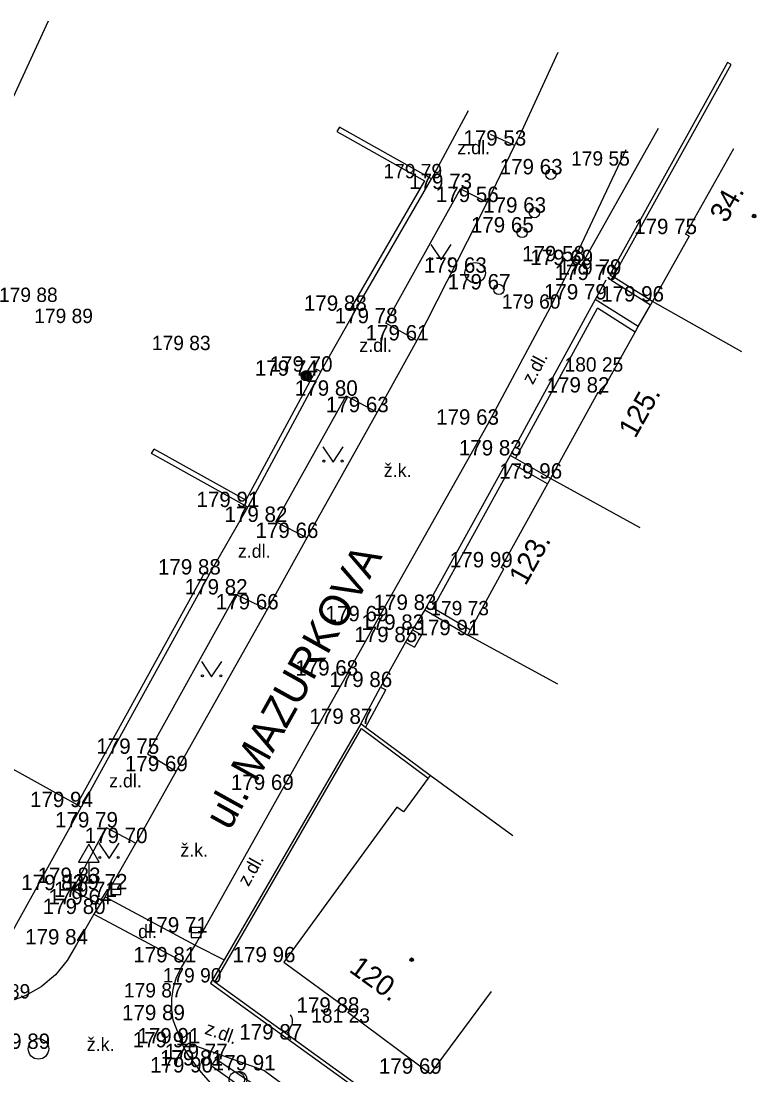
# Model space of a CAD drawing. Extents: x -537755 to -537431, y -1180722 to -1180510.
# Drawn here: x -537645.9 to -537610, y -1180566.9 to -1180515.4 of the extents above; entities that cross this region are included whole.
import ezdxf

# ---------------------------------------------------------------- set-up
doc = ezdxf.new("R2010")
doc.units = 0
for name, color, linetype in [('Vrstva 1', 7, 'Continuous'), ('Vrstva 10', 7, 'Continuous'), ('Vrstva 11', 7, 'Continuous'), ('Vrstva 21', 7, 'Continuous'), ('Vrstva 24', 7, 'Continuous'), ('Vrstva 25', 7, 'Continuous'), ('Vrstva 27', 7, 'Continuous'), ('Vrstva 28', 7, 'Continuous'), ('Vrstva 3', 7, 'Continuous'), ('Vrstva 34', 7, 'Continuous'), ('Vrstva 36', 7, 'Continuous'), ('Vrstva 39', 7, 'Continuous'), ('Vrstva 40', 7, 'Continuous'), ('Vrstva 47', 7, 'Continuous'), ('Vrstva 49', 7, 'Continuous'), ('Vrstva 5', 7, 'Continuous'), ('Vrstva 7', 7, 'Continuous'), ('Vrstva 8', 7, 'Continuous')]:
    doc.layers.add(name, color=color, linetype=linetype)

msp = doc.modelspace()

# ---------------------------------------------------------------- linework, layer by layer
at = {"layer": 'Vrstva 1'}
for p, q in [((-537621.821, -1180521.513), (-537621.821, -1180521.513)), ((-537616.732, -1180522.488), (-537616.732, -1180522.488)), ((-537625.887, -1180523.104), (-537625.887, -1180523.104)), ((-537625.88, -1180523.14), (-537625.88, -1180523.14)), ((-537620.049, -1180522.914), (-537620.049, -1180522.914)), ((-537624.465, -1180523.627), (-537624.465, -1180523.627)), ((-537623.163, -1180524.264), (-537623.163, -1180524.264)), ((-537620.853, -1180524.784), (-537620.853, -1180524.784)), ((-537621.51, -1180525.74), (-537621.51, -1180525.74)), ((-537621.455, -1180525.751), (-537621.455, -1180525.751)), ((-537613.49, -1180525.83), (-537613.49, -1180525.83)), ((-537618.955, -1180527.156), (-537618.955, -1180527.156)), ((-537623.746, -1180527.714), (-537623.746, -1180527.714)), ((-537618.559, -1180527.34), (-537618.559, -1180527.34)), ((-537617.18, -1180527.81), (-537617.18, -1180527.81)), ((-537617.37, -1180528.07), (-537617.37, -1180528.07)), ((-537622.587, -1180528.528), (-537622.587, -1180528.528)), ((-537644.64, -1180529.14), (-537644.64, -1180529.14)), ((-537617.89, -1180529.02), (-537617.89, -1180529.02)), ((-537615.1, -1180529.12), (-537615.1, -1180529.12)), ((-537629.6, -1180529.57), (-537629.6, -1180529.57)), ((-537620.113, -1180529.467), (-537620.113, -1180529.467)), ((-537642.92, -1180530.17), (-537642.92, -1180530.17)), ((-537628.097, -1180530.179), (-537628.097, -1180530.179)), ((-537626.588, -1180531.018), (-537626.588, -1180531.018)), ((-537637.18, -1180531.49), (-537637.18, -1180531.49)), ((-537632.19, -1180532.84), (-537632.19, -1180532.84)), ((-537631.99, -1180532.74), (-537631.99, -1180532.74)), ((-537631.27, -1180532.54), (-537631.27, -1180532.54)), ((-537617.05, -1180532.54), (-537617.05, -1180532.54)), ((-537630.041, -1180533.715), (-537630.041, -1180533.715)), ((-537617.76, -1180533.56), (-537617.76, -1180533.56)), ((-537628.528, -1180534.519), (-537628.528, -1180534.519)), ((-537623.36, -1180535.47), (-537623.36, -1180535.47)), ((-537623.15, -1180535.129), (-537623.15, -1180535.129)), ((-537629.16, -1180535.58), (-537629.16, -1180535.58)), ((-537622.04, -1180536.63), (-537622.04, -1180536.63)), ((-537620.07, -1180537.76), (-537620.07, -1180537.76)), ((-537634.84, -1180539.15), (-537634.84, -1180539.15)), ((-537633.472, -1180539.873), (-537633.472, -1180539.873)), ((-537631.96, -1180540.657), (-537631.96, -1180540.657)), ((-537622.48, -1180542.09), (-537622.48, -1180542.09)), ((-537636.72, -1180542.44), (-537636.72, -1180542.44)), ((-537635.415, -1180543.413), (-537635.415, -1180543.413)), ((-537633.898, -1180544.141), (-537633.898, -1180544.141)), ((-537626.2, -1180544.17), (-537626.2, -1180544.17)), ((-537628.546, -1180544.722), (-537628.546, -1180544.722)), ((-537623.6, -1180544.43), (-537623.6, -1180544.43)), ((-537626.8, -1180545.14), (-537626.8, -1180545.14)), ((-537627.14, -1180545.74), (-537627.14, -1180545.74)), ((-537624.11, -1180545.4), (-537624.11, -1180545.4)), ((-537630.02, -1180547.37), (-537630.02, -1180547.37)), ((-537628.36, -1180547.93), (-537628.36, -1180547.93)), ((-537630.78, -1180548.65), (-537630.78, -1180548.65)), ((-537630.95, -1180549), (-537630.95, -1180549)), ((-537629.33, -1180549.73), (-537629.33, -1180549.73)), ((-537639.725, -1180551.19), (-537639.725, -1180551.19)), ((-537638.33, -1180552.039), (-537638.33, -1180552.039)), ((-537633.161, -1180552.953), (-537633.161, -1180552.953)), ((-537642.96, -1180553.79), (-537642.96, -1180553.79)), ((-537641.739, -1180554.78), (-537641.739, -1180554.78)), ((-537640.294, -1180555.547), (-537640.294, -1180555.547)), ((-537642.59, -1180557.49), (-537642.59, -1180557.49)), ((-537643.39, -1180557.84), (-537643.39, -1180557.84)), ((-537641.275, -1180557.801), (-537641.275, -1180557.801)), ((-537642.06, -1180558.54), (-537642.06, -1180558.54)), ((-537641.788, -1180558.176), (-537641.788, -1180558.176)), ((-537641.754, -1180558.18), (-537641.754, -1180558.18)), ((-537642.342, -1180559.006), (-537642.342, -1180559.006)), ((-537637.355, -1180559.909), (-537637.355, -1180559.909)), ((-537643.199, -1180560.493), (-537643.199, -1180560.493)), ((-537637.372, -1180560.473), (-537637.372, -1180560.473)), ((-537637.75, -1180561.22), (-537637.75, -1180561.22)), ((-537637.921, -1180561.366), (-537637.921, -1180561.366)), ((-537633.08, -1180561.36), (-537633.08, -1180561.36)), ((-537636.652, -1180562.347), (-537636.652, -1180562.347)), ((-537636.65, -1180562.38), (-537636.65, -1180562.38)), ((-537636.55, -1180562.35), (-537636.55, -1180562.35)), ((-537638.545, -1180563.077), (-537638.545, -1180563.077)), ((-537629.96, -1180563.82), (-537629.96, -1180563.82)), ((-537638.472, -1180564.188), (-537638.472, -1180564.188)), ((-537629.41, -1180564.31), (-537629.41, -1180564.31)), ((-537637.724, -1180565.319), (-537637.724, -1180565.319)), ((-537632.75, -1180565.13), (-537632.75, -1180565.13)), ((-537645.047, -1180565.588), (-537645.047, -1180565.588)), ((-537637.951, -1180565.512), (-537637.951, -1180565.512)), ((-537636.39, -1180566.09), (-537636.39, -1180566.09)), ((-537637.103, -1180566.74), (-537637.103, -1180566.74)), ((-537636.62, -1180566.4), (-537636.62, -1180566.4)), ((-537634.047, -1180566.636), (-537634.047, -1180566.636)), ((-537625.94, -1180566.8), (-537625.94, -1180566.8))]:
    msp.add_line(p, q, dxfattribs=at)
at = {"layer": 'Vrstva 10'}
for p, q in [((-537621.821, -1180521.513), (-537623.163, -1180524.264)), ((-537618.955, -1180527.156), (-537616.376, -1180521.7)), ((-537623.163, -1180524.264), (-537626.588, -1180531.018)), ((-537620.2, -1180529.637), (-537618.955, -1180527.156)), ((-537623.15, -1180535.129), (-537620.2, -1180529.637)), ((-537626.588, -1180531.018), (-537628.528, -1180534.519)), ((-537628.528, -1180534.519), (-537631.96, -1180540.657)), ((-537628.546, -1180544.722), (-537623.15, -1180535.129)), ((-537631.96, -1180540.657), (-537633.898, -1180544.141)), ((-537633.898, -1180544.141), (-537638.33, -1180552.039)), ((-537630.02, -1180547.37), (-537628.546, -1180544.722)), ((-537633.161, -1180552.953), (-537630.02, -1180547.37)), ((-537638.33, -1180552.039), (-537640.294, -1180555.547)), ((-537637.396, -1180560.52), (-537633.161, -1180552.953)), ((-537641.788, -1180558.176), (-537640.294, -1180555.547)), ((-537641.788, -1180558.176), (-537637.396, -1180560.52)), ((-537642.342, -1180559.006), (-537643.199, -1180560.493)), ((-537642.342, -1180559.006), (-537637.921, -1180561.366)), ((-537637.921, -1180561.366), (-537637.396, -1180560.52))]:
    msp.add_line(p, q, dxfattribs=at)
for points in [[(-537619.715, -1180516.973), (-537621.478, -1180520.825), (-537621.821, -1180521.513)], [(-537642.06, -1180558.54), (-537642.342, -1180559.006)], [(-537641.788, -1180558.176), (-537642.06, -1180558.54)], [(-537643.199, -1180560.493), (-537643.645, -1180561.278), (-537644.223, -1180561.973), (-537644.914, -1180562.555), (-537645.697, -1180563.006), (-537646.547, -1180563.313), (-537647.438, -1180563.465), (-537648.341, -1180563.458), (-537648.663, -1180563.416)], [(-537638.472, -1180564.188), (-537638.55, -1180563.66), (-537638.549, -1180563.127), (-537638.468, -1180562.599), (-537638.31, -1180562.09), (-537638.077, -1180561.61), (-537637.921, -1180561.366)], [(-537637.103, -1180566.74), (-537637.707, -1180565.933), (-537637.951, -1180565.512), (-537638.472, -1180564.188)], [(-537634.903, -1180568.594), (-537635.829, -1180567.981), (-537636.657, -1180567.242), (-537637.103, -1180566.74)]]:
    msp.add_lwpolyline(points, dxfattribs=at)
at = {"layer": 'Vrstva 11'}
for p, q in [((-537624.089, -1180519.81), (-537625.88, -1180523.14)), ((-537621.821, -1180521.513), (-537623.003, -1180520.976)), ((-537618.559, -1180527.34), (-537614.807, -1180520.662)), ((-537628.097, -1180530.179), (-537624.465, -1180523.627)), ((-537624.465, -1180523.627), (-537623.163, -1180524.264)), ((-537618.955, -1180527.156), (-537618.559, -1180527.34)), ((-537626.588, -1180531.018), (-537628.097, -1180530.179)), ((-537633.472, -1180539.873), (-537630.041, -1180533.715)), ((-537630.041, -1180533.715), (-537628.528, -1180534.519)), ((-537631.96, -1180540.657), (-537633.472, -1180539.873)), ((-537635.415, -1180543.413), (-537639.725, -1180551.19)), ((-537633.898, -1180544.141), (-537635.415, -1180543.413)), ((-537639.725, -1180551.19), (-537638.33, -1180552.039)), ((-537643.39, -1180557.84), (-537641.739, -1180554.78)), ((-537641.739, -1180554.78), (-537640.294, -1180555.547)), ((-537643.39, -1180557.84), (-537642.06, -1180558.54)), ((-537637.396, -1180560.52), (-537635.993, -1180561.245)), ((-537623.722, -1180574.291), (-537634.047, -1180566.636))]:
    msp.add_line(p, q, dxfattribs=at)
msp.add_lwpolyline([(-537634.047, -1180566.636), (-537637.724, -1180565.319), (-537637.951, -1180565.512)], dxfattribs=at)
at = {"layer": 'Vrstva 21'}
msp.add_lwpolyline([(-537636.62, -1180566.4), (-537634.122, -1180568.192), (-537633.84, -1180567.8), (-537636.39, -1180566.09), (-537636.62, -1180566.4)], dxfattribs=at)
at = {"layer": 'Vrstva 24'}
for centre, start, end in [((-537633.15, -1180564.231), 323.1301, 36.8699), ((-537632.35, -1180564.831), 143.1301, 216.8699)]:
    msp.add_arc(centre, 0.5, start, end, dxfattribs=at)
at = {"layer": 'Vrstva 25'}
for radius in [0.25, 0.2, 0.15, 0.1, 0.05]:
    msp.add_circle((-537631.99, -1180532.74), radius, dxfattribs=at)
at = {"layer": 'Vrstva 27'}
for p, q in [((-537641.525, -1180557.801), (-537641.025, -1180557.801)), ((-537637.605, -1180559.909), (-537637.105, -1180559.909))]:
    msp.add_line(p, q, dxfattribs=at)
for points in [[(-537641.525, -1180558.051), (-537641.025, -1180558.051), (-537641.025, -1180557.551), (-537641.525, -1180557.551)], [(-537637.605, -1180560.159), (-537637.105, -1180560.159), (-537637.105, -1180559.659), (-537637.605, -1180559.659)]]:
    msp.add_lwpolyline(points, close=True, dxfattribs=at)
for centre in [(-537623.746, -1180527.714), (-537645.047, -1180565.588)]:
    msp.add_circle(centre, 0.5, dxfattribs=at)
at = {"layer": 'Vrstva 28'}
for centre in [(-537620.049, -1180522.914), (-537620.853, -1180524.784), (-537621.455, -1180525.751), (-537622.587, -1180528.528)]:
    msp.add_circle(centre, 0.25, dxfattribs=at)
at = {"layer": 'Vrstva 34'}
for p, q in [((-537642.59, -1180556.474), (-537642.59, -1180557.49)), ((-537642.84, -1180557.49), (-537642.34, -1180557.49))]:
    msp.add_line(p, q, dxfattribs=at)
msp.add_lwpolyline([(-537643.09, -1180556.474), (-537642.09, -1180556.474), (-537642.59, -1180555.606)], close=True, dxfattribs=at)
at = {"layer": 'Vrstva 36'}
for points in [[(-537625.911, -1180526.333), (-537625.411, -1180527.083), (-537624.911, -1180526.333)], [(-537631.178, -1180536.202), (-537630.678, -1180536.952), (-537630.178, -1180536.202)], [(-537637.103, -1180546.685), (-537636.603, -1180547.435), (-537636.103, -1180546.685)], [(-537642.107, -1180555.55), (-537641.607, -1180556.3), (-537641.107, -1180555.55)]]:
    msp.add_lwpolyline(points, dxfattribs=at)
for centre, radius in [((-537625.861, -1180527.033), 0.05), ((-537624.962, -1180527.033), 0.05), ((-537631.128, -1180536.902), 0.05), ((-537630.229, -1180536.902), 0.05), ((-537637.053, -1180547.385), 0.05), ((-537636.154, -1180547.385), 0.05), ((-537642.057, -1180556.25), 0.05), ((-537641.158, -1180556.25), 0.05), ((-537635.371, -1180567.076), 0.375)]:
    msp.add_circle(centre, radius, dxfattribs=at)
msp.add_arc((-537635.246, -1180567.076), 0.375, 260.4059, 99.5941, dxfattribs=at)
at = {"layer": 'Vrstva 39'}
for centre, radius in [((-537610.139, -1180524.95), 0.09), ((-537610.139, -1180524.95), 0.0398), ((-537626.843, -1180561.234), 0.09), ((-537626.843, -1180561.234), 0.0398)]:
    msp.add_circle(centre, radius, dxfattribs=at)
at = {"layer": 'Vrstva 5'}
for p, q in [((-537644.571, -1180515.434), (-537651.348, -1180530.109)), ((-537611.15, -1180521.66), (-537613.49, -1180525.83)), ((-537613.31, -1180525.931), (-537615.1, -1180529.12)), ((-537613.31, -1180525.931), (-537613.49, -1180525.83)), ((-537615.786, -1180530.345), (-537615.198, -1180529.295)), ((-537615.198, -1180529.295), (-537615.1, -1180529.12)), ((-537610.74, -1180531.567), (-537615.1, -1180529.12)), ((-537615.933, -1180530.607), (-537615.786, -1180530.345)), ((-537617.628, -1180533.632), (-537615.933, -1180530.607)), ((-537617.76, -1180533.56), (-537620.07, -1180537.76)), ((-537617.628, -1180533.632), (-537617.76, -1180533.56)), ((-537620.216, -1180538.022), (-537622.48, -1180542.09)), ((-537620.07, -1180537.76), (-537620.216, -1180538.022)), ((-537615.689, -1180540.17), (-537620.07, -1180537.76)), ((-537623.966, -1180545.136), (-537622.349, -1180542.163)), ((-537622.349, -1180542.163), (-537622.48, -1180542.09)), ((-537624.11, -1180545.4), (-537623.966, -1180545.136)), ((-537619.718, -1180547.789), (-537624.11, -1180545.4)), ((-537647.333, -1180551.366), (-537643.178, -1180553.669)), ((-537626.034, -1180552.372), (-537627.238, -1180554.023)), ((-537625.946, -1180552.251), (-537626.034, -1180552.372)), ((-537621.906, -1180555.196), (-537625.946, -1180552.251)), ((-537643.178, -1180553.669), (-537642.96, -1180553.79)), ((-537627.561, -1180553.787), (-537633.08, -1180561.36)), ((-537627.238, -1180554.023), (-537627.561, -1180553.787)), ((-537633.08, -1180561.36), (-537629.87, -1180563.699)), ((-537622.962, -1180562.783), (-537625.94, -1180566.8)), ((-537629.87, -1180563.699), (-537629.96, -1180563.82)), ((-537625.94, -1180566.8), (-537629.96, -1180563.82))]:
    msp.add_line(p, q, dxfattribs=at)
for points in [[(-537644.596, -1180556.742), (-537642.96, -1180553.79)], [(-537646.79, -1180560.7), (-537644.596, -1180556.742)]]:
    msp.add_lwpolyline(points, dxfattribs=at)
at = {"layer": 'Vrstva 7'}
for p, q in [((-537617.01, -1180527.917), (-537611.257, -1180517.551)), ((-537630.491, -1180520.821), (-537626.223, -1180523.233)), ((-537626.223, -1180523.233), (-537629.816, -1180529.445)), ((-537615.1, -1180529.12), (-537617.01, -1180527.917)), ((-537617.89, -1180529.02), (-537622.04, -1180536.63)), ((-537615.786, -1180530.345), (-537617.89, -1180529.02)), ((-537621.78, -1180536.779), (-537617.78, -1180529.444)), ((-537615.933, -1180530.607), (-537617.78, -1180529.444)), ((-537631.49, -1180532.421), (-537634.94, -1180538.808)), ((-537634.94, -1180538.808), (-537639.406, -1180536.321)), ((-537622.04, -1180536.63), (-537626.2, -1180544.17)), ((-537625.796, -1180544.059), (-537621.925, -1180537.042)), ((-537620.216, -1180538.022), (-537621.925, -1180537.042)), ((-537636.939, -1180542.32), (-537643.178, -1180553.669)), ((-537626.2, -1180544.17), (-537624.11, -1180545.4)), ((-537625.796, -1180544.059), (-537623.966, -1180545.136)), ((-537626.8, -1180545.14), (-537627.14, -1180545.74)), ((-537626.8, -1180545.14), (-537626.365, -1180545.387)), ((-537627.14, -1180545.74), (-537626.705, -1180545.987)), ((-537626.365, -1180545.387), (-537626.705, -1180545.987)), ((-537629.087, -1180549.911), (-537628.096, -1180548.072)), ((-537636.452, -1180562.338), (-537629.285, -1180549.951)), ((-537629.285, -1180549.951), (-537626.034, -1180552.372)), ((-537636.65, -1180562.38), (-537627.11, -1180569.26)), ((-537627.022, -1180569.138), (-537636.452, -1180562.338))]:
    msp.add_line(p, q, dxfattribs=at)
for points in [[(-537611.257, -1180517.551), (-537611.43, -1180517.45), (-537617.18, -1180527.81), (-537617.01, -1180527.917)], [(-537625.88, -1180523.14), (-537630.368, -1180520.603), (-537630.491, -1180520.821)], [(-537629.6, -1180529.57), (-537625.88, -1180523.14)], [(-537615.198, -1180529.295), (-537617.129, -1180528.079), (-537617.01, -1180527.917)], [(-537629.816, -1180529.445), (-537629.6, -1180529.57)], [(-537631.49, -1180532.421), (-537631.27, -1180532.54)], [(-537631.27, -1180532.54), (-537634.84, -1180539.15)], [(-537639.528, -1180536.539), (-537639.406, -1180536.321)], [(-537634.84, -1180539.15), (-537639.528, -1180536.539)], [(-537620.07, -1180537.76), (-537621.78, -1180536.779), (-537622.04, -1180536.63)], [(-537636.72, -1180542.44), (-537642.96, -1180553.79)], [(-537636.939, -1180542.32), (-537636.72, -1180542.44)], [(-537629.33, -1180549.73), (-537628.36, -1180547.93), (-537628.096, -1180548.072)], [(-537629.33, -1180549.73), (-537635.993, -1180561.245)], [(-537625.946, -1180552.251), (-537629.087, -1180549.911), (-537629.33, -1180549.73)], [(-537635.993, -1180561.245), (-537636.65, -1180562.38)]]:
    msp.add_lwpolyline(points, dxfattribs=at)
at = {"layer": 'Vrstva 8'}
for p, q in [((-537617.37, -1180528.07), (-537617.89, -1180529.02)), ((-537631.27, -1180532.54), (-537629.6, -1180529.57)), ((-537636.72, -1180542.44), (-537634.84, -1180539.15)), ((-537626.2, -1180544.17), (-537626.8, -1180545.14)), ((-537627.14, -1180545.74), (-537628.36, -1180547.93))]:
    msp.add_line(p, q, dxfattribs=at)

# ---------------------------------------------------------------- texts
at = {"layer": 'Vrstva 3'}
for s, height, p in [('179 53 ', 0.75, (-537624.321, -1180521.513)), ('179 63 ', 0.75, (-537622.549, -1180522.914)), ('179 55 ', 0.7, (-537619.065, -1180522.488)), ('179 79 ', 0.7, (-537628.22, -1180523.104)), ('179 73 ', 0.75, (-537626.965, -1180523.627)), ('179 56 ', 0.75, (-537625.663, -1180524.264)), ('179 63 ', 0.75, (-537623.353, -1180524.784)), ('179 65 ', 0.75, (-537623.955, -1180525.751)), ('179 75 ', 0.75, (-537615.99, -1180525.83)), ('179 58 ', 0.75, (-537621.455, -1180527.156)), ('179 69 ', 0.75, (-537621.059, -1180527.34)), ('179 63 ', 0.75, (-537626.246, -1180527.714)), ('179 79 ', 0.75, (-537619.87, -1180528.07)), ('179 79 ', 0.75, (-537619.68, -1180527.81)), ('179 67 ', 0.75, (-537625.087, -1180528.528)), ('179 79 ', 0.75, (-537620.39, -1180529.02)), ('179 88 ', 0.7, (-537646.974, -1180529.14)), ('179 88 ', 0.75, (-537632.1, -1180529.57)), ('179 60 ', 0.7, (-537622.446, -1180529.467)), ('179 96 ', 0.75, (-537617.6, -1180529.12)), ('179 89 ', 0.7, (-537645.254, -1180530.17)), ('179 78 ', 0.75, (-537630.597, -1180530.179)), ('179 61 ', 0.75, (-537629.088, -1180531.018)), ('179 83 ', 0.7, (-537639.514, -1180531.49)), ('179 70 ', 0.75, (-537633.77, -1180532.54)), ('180 25 ', 0.7, (-537619.384, -1180532.54)), ('179 74 ', 0.75, (-537634.49, -1180532.74)), ('179 80 ', 0.75, (-537632.541, -1180533.715)), ('179 82 ', 0.75, (-537620.26, -1180533.56)), ('179 63 ', 0.75, (-537631.028, -1180534.519)), ('179 63 ', 0.75, (-537625.65, -1180535.129)), ('179 83 ', 0.75, (-537624.54, -1180536.63)), ('179 96 ', 0.75, (-537622.57, -1180537.76)), ('179 91 ', 0.75, (-537637.34, -1180539.15)), ('179 82 ', 0.75, (-537635.972, -1180539.873)), ('179 66 ', 0.75, (-537634.46, -1180540.657)), ('179 88 ', 0.75, (-537639.22, -1180542.44)), ('179 99 ', 0.75, (-537624.98, -1180542.09)), ('179 82 ', 0.75, (-537637.915, -1180543.413)), ('179 66 ', 0.75, (-537636.398, -1180544.141)), ('179 83 ', 0.75, (-537628.7, -1180544.17)), ('179 73 ', 0.7, (-537625.934, -1180544.43)), ('179 69 ', 0.75, (-537631.046, -1180544.722)), ('179 83 ', 0.75, (-537629.3, -1180545.14)), ('179 91 ', 0.75, (-537626.61, -1180545.4)), ('179 85 ', 0.75, (-537629.64, -1180545.74)), ('179 68 ', 0.75, (-537632.52, -1180547.37)), ('179 86 ', 0.75, (-537630.86, -1180547.93)), ('179 87 ', 0.75, (-537631.83, -1180549.73)), ('179 75 ', 0.75, (-537642.225, -1180551.19)), ('179 69 ', 0.75, (-537640.83, -1180552.039)), ('179 69 ', 0.75, (-537635.661, -1180552.953)), ('179 94 ', 0.75, (-537645.46, -1180553.79)), ('179 79 ', 0.75, (-537644.239, -1180554.78)), ('179 70 ', 0.75, (-537642.794, -1180555.547)), ('179 82 ', 0.75, (-537645.89, -1180557.84)), ('179 83 ', 0.75, (-537645.09, -1180557.49)), ('179 72 ', 0.75, (-537643.775, -1180557.801)), ('179 71 ', 0.75, (-537644.288, -1180558.176)), ('179 64 ', 0.75, (-537644.56, -1180558.54)), ('179 80 ', 0.75, (-537644.842, -1180559.006)), ('179 71 ', 0.75, (-537639.855, -1180559.909)), ('179 84 ', 0.75, (-537645.699, -1180560.493)), ('179 81 ', 0.75, (-537640.421, -1180561.366)), ('179 96 ', 0.75, (-537635.58, -1180561.36)), ('179 90 ', 0.7, (-537638.985, -1180562.347)), ('179 89 ', 0.7, (-537648.312, -1180563.127)), ('179 87 ', 0.7, (-537640.878, -1180563.077)), ('179 88 ', 0.75, (-537632.46, -1180563.82)), ('179 89 ', 0.75, (-537640.972, -1180564.188)), ('181 23 ', 0.7, (-537631.744, -1180564.31)), ('179 89 ', 0.75, (-537647.547, -1180565.588)), ('179 91 ', 0.75, (-537640.451, -1180565.512)), ('179 91 ', 0.75, (-537640.224, -1180565.319)), ('179 87 ', 0.75, (-537635.25, -1180565.13)), ('179 77 ', 0.75, (-537638.89, -1180566.09)), ('179 81 ', 0.75, (-537639.12, -1180566.4)), ('179 91 ', 0.75, (-537636.547, -1180566.636)), ('179 90 ', 0.75, (-537639.603, -1180566.74)), ('179 69 ', 0.75, (-537628.44, -1180566.8))]:
    msp.add_text(s, height=height, dxfattribs=at).set_placement(p)
at = {"layer": 'Vrstva 40'}
for s, p in [('z.dl.', (-537624.615, -1180521.929)), ('z.dl.', (-537629.397, -1180531.575)), ('ž.k.', (-537628.203, -1180537.678)), ('z.dl.', (-537635.321, -1180541.623)), ('z.dl.', (-537641.601, -1180552.828)), ('ž.k.', (-537638.125, -1180556.212)), ('dl.', (-537640.187, -1180560.181)), ('ž.k.', (-537642.691, -1180565.687))]:
    msp.add_text(s, height=0.65, dxfattribs=at).set_placement(p)
for rotation, p in [(61.7865, (-537620.932, -1180533.209)), (60.7523, (-537634.803, -1180557.7)), (340.2939, (-537636.981, -1180564.842))]:
    msp.add_text('z.dl.', height=0.65, rotation=rotation, dxfattribs=at).set_placement(p)
at = {"layer": 'Vrstva 47'}
for s, rotation, p in [('34.', 60.701, (-537611.49, -1180525.331)), ('125.', 60.7388, (-537615.935, -1180535.837)), ('123.', 60.9005, (-537621.285, -1180543.026)), ('120.', 323.9207, (-537629.945, -1180561.789))]:
    msp.add_text(s, height=1, rotation=rotation, dxfattribs=at).set_placement(p)
at = {"layer": 'Vrstva 49'}
msp.add_text('ul. MAZURKOVA', height=1.5, rotation=60.8943, dxfattribs=at).set_placement((-537635.731, -1180554.98))

doc.saveas('drawing.dxf')
